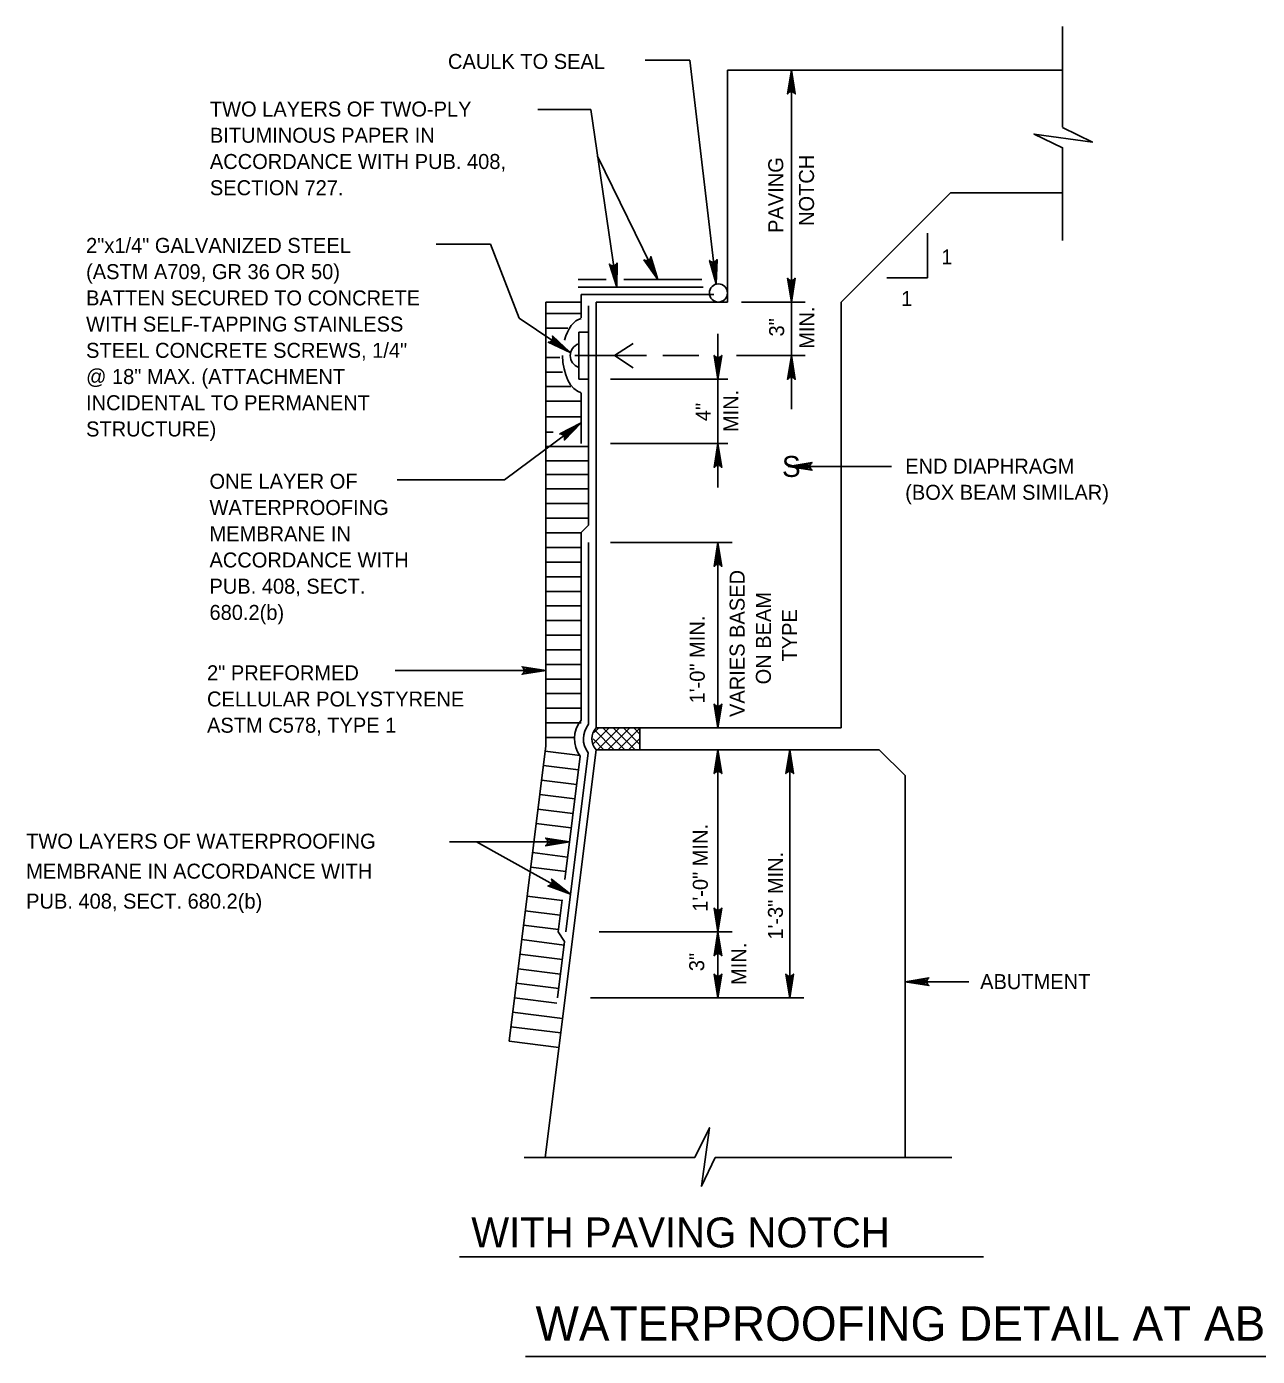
# Model space of a CAD drawing. Extents: x 638653 to 642302, y 298557 to 300414.
# Drawn here: x 641555.5 to 641801.9, y 299693.6 to 299959.8 of the extents above; entities that cross this region are included whole.
import ezdxf

# ---------------------------------------------------------------- set-up
doc = ezdxf.new("R2010")
doc.units = 0
doc.layers.add('1', color=7, linetype='Continuous')

msp = doc.modelspace()

# ---------------------------------------------------------------- linework, layer by layer
at = {"layer": '1'}
for p, q in [((641762.9, 299959.81), (641762.9, 299939.69)), ((641688.27, 299953.06), (641679.3, 299953.06)), ((641688.27, 299953.06), (641693.52, 299908.35)), ((641762.9, 299951.12), (641695.83, 299951.12)), ((641695.83, 299951.12), (641695.83, 299904.66)), ((641708.58, 299951.12), (641708.58, 299904.66)), ((641668.43, 299943.24), (641657.85, 299943.24)), ((641668.43, 299943.24), (641673.61, 299907.66)), ((641762.9, 299916.97), (641762.9, 299935.58)), ((641669.79, 299933.87), (641681.85, 299909.16)), ((641718.59, 299904.66), (641740.48, 299926.55)), ((641762.9, 299926.55), (641740.48, 299926.55)), ((641637.45, 299916.24), (641648.36, 299916.24)), ((641648.36, 299916.24), (641654.07, 299901.48)), ((641735.83, 299909.53), (641735.83, 299918.46)), ((641671.5, 299909.16), (641665.9, 299909.16)), ((641690.65, 299909.16), (641675.01, 299909.16)), ((641727.67, 299909.53), (641735.83, 299909.53)), ((641690.9, 299907.66), (641665.9, 299907.66)), ((641693.08, 299906.16), (641666.5, 299906.16)), ((641666.5, 299901.49), (641666.5, 299906.16)), ((641666.5, 299904.66), (641659.43, 299904.66)), ((641659.43, 299815.83), (641659.43, 299904.66)), ((641666.5, 299902.08), (641666.5, 299904.66)), ((641668, 299860.04), (641668, 299903.95)), ((641669.5, 299819.44), (641669.5, 299904.66)), ((641695.83, 299904.66), (641669.5, 299904.66)), ((641711.33, 299904.66), (641698.6, 299904.66)), ((641708.58, 299904.66), (641708.58, 299893.95)), ((641718.59, 299819.44), (641718.59, 299904.66)), ((641654.07, 299901.48), (641664.3, 299894.6)), ((641659.43, 299902.37), (641666.5, 299902.37)), ((641659.43, 299899.44), (641663.83, 299899.44)), ((641668, 299898.67), (641666.02, 299898.67)), ((641666.02, 299889.23), (641666.02, 299898.67)), ((641693.89, 299889.23), (641693.89, 299898.32)), ((641666.02, 299891.59), (641666.02, 299896.32)), ((641676.94, 299896.41), (641673.16, 299893.95)), ((641659.43, 299893.59), (641662.26, 299893.59)), ((641665.22, 299893.95), (641679.6, 299893.95)), ((641676.94, 299891.49), (641673.16, 299893.95)), ((641682.84, 299893.95), (641690.08, 299893.95)), ((641697.58, 299893.95), (641711.33, 299893.95)), ((641708.58, 299893.95), (641708.58, 299883.24)), ((641659.43, 299890.67), (641662.75, 299890.67)), ((641659.43, 299887.74), (641664.43, 299887.74)), ((641668, 299889.23), (641666.02, 299889.23)), ((641672.38, 299889.23), (641695.88, 299889.23)), ((641693.89, 299876.34), (641693.89, 299889.23)), ((641659.43, 299884.81), (641666.5, 299884.81)), ((641666.5, 299876.34), (641666.5, 299886.41)), ((641659.43, 299881.69), (641666.5, 299881.69)), ((641666.5, 299880.52), (641651.18, 299869.12)), ((641659.43, 299878.66), (641660.86, 299878.66)), ((641672.38, 299876.34), (641695.88, 299876.34)), ((641693.89, 299867.56), (641693.89, 299876.34)), ((641659.43, 299875.74), (641668, 299875.74)), ((641659.43, 299872.91), (641668, 299872.91)), ((641708.57, 299871.76), (641728.61, 299871.76)), ((641629.65, 299869.12), (641651.18, 299869.12)), ((641659.43, 299870.18), (641668, 299870.18)), ((641659.43, 299867.26), (641668, 299867.26)), ((641659.43, 299864.33), (641668, 299864.33)), ((641659.43, 299861.4), (641668, 299861.4)), ((641666.5, 299858.54), (641668, 299860.04)), ((641659.43, 299858.48), (641666.5, 299858.48)), ((641666.5, 299858.54), (641666.5, 299821)), ((641659.43, 299855.55), (641666.5, 299855.55)), ((641668, 299820.17), (641668, 299856.54)), ((641672.38, 299856.54), (641696.71, 299856.54)), ((641693.89, 299856.54), (641693.89, 299819.44)), ((641659.43, 299852.63), (641666.5, 299852.63)), ((641659.43, 299849.7), (641666.5, 299849.7)), ((641659.43, 299846.77), (641666.5, 299846.77)), ((641659.43, 299843.85), (641666.5, 299843.85)), ((641659.43, 299840.92), (641666.5, 299840.92)), ((641659.43, 299838), (641666.5, 299838)), ((641659.43, 299835.07), (641666.5, 299835.07)), ((641629.24, 299830.92), (641659.43, 299830.92)), ((641659.43, 299832.14), (641666.5, 299832.14)), ((641659.43, 299829.22), (641666.5, 299829.22)), ((641659.43, 299826.29), (641666.5, 299826.29)), ((641659.43, 299823.37), (641666.5, 299823.37)), ((641659.43, 299820.44), (641666.5, 299820.44)), ((641659.43, 299817.51), (641665.16, 299817.51)), ((641669, 299816.34), (641672.11, 299819.44)), ((641669.09, 299818.49), (641670.04, 299819.44)), ((641673.14, 299815.05), (641669.25, 299818.95)), ((641718.59, 299819.44), (641669.5, 299819.44)), ((641669.79, 299815.05), (641674.18, 299819.44)), ((641675.21, 299815.05), (641670.82, 299819.44)), ((641671.86, 299815.05), (641676.25, 299819.44)), ((641677.28, 299815.05), (641672.89, 299819.44)), ((641673.93, 299815.05), (641678.32, 299819.44)), ((641678.27, 299816.13), (641674.96, 299819.44)), ((641678.27, 299818.2), (641677.03, 299819.44)), ((641678.27, 299815.05), (641678.27, 299819.44)), ((641652.05, 299756.72), (641659.43, 299815.83)), ((641659.29, 299733.42), (641669.5, 299815.05)), ((641659.31, 299814.79), (641666.31, 299813.92)), ((641671.07, 299815.05), (641668.91, 299817.22)), ((641726.19, 299815.05), (641669.5, 299815.05)), ((641676, 299815.05), (641678.27, 299817.33)), ((641678.06, 299815.05), (641678.27, 299815.26)), ((641693.89, 299778.61), (641693.89, 299815.05)), ((641708.25, 299765.38), (641708.25, 299815.05)), ((641726.19, 299815.05), (641731.35, 299809.9)), ((641663.23, 299789.08), (641666.31, 299813.75)), ((641663.43, 299778.61), (641667.91, 299814.44)), ((641658.94, 299811.89), (641665.95, 299811.01)), ((641731.35, 299733.42), (641731.35, 299809.9)), ((641658.58, 299808.98), (641665.59, 299808.11)), ((641658.22, 299806.08), (641665.22, 299805.21)), ((641657.85, 299803.18), (641664.86, 299802.3)), ((641657.49, 299800.27), (641664.5, 299799.4)), ((641640.15, 299796.62), (641664.17, 299796.62)), ((641664.37, 299786.18), (641645.55, 299796.62)), ((641656.76, 299794.47), (641663.77, 299793.59)), ((641656.4, 299791.56), (641663.41, 299790.69)), ((641655.68, 299785.76), (641662.68, 299784.88)), ((641655.31, 299782.85), (641662.32, 299781.98)), ((641661.92, 299778.6), (641662.72, 299785.01)), ((641654.95, 299779.95), (641661.97, 299779.07)), ((641661.92, 299778.6), (641663.18, 299776.65)), ((641670.09, 299778.61), (641696.71, 299778.61)), ((641693.89, 299765.38), (641693.89, 299778.61)), ((641654.59, 299777.05), (641663.1, 299775.98)), ((641661.78, 299765.38), (641663.18, 299776.65)), ((641654.22, 299774.14), (641662.74, 299773.08)), ((641653.86, 299771.24), (641662.37, 299770.17)), ((641653.5, 299768.34), (641662.01, 299767.27)), ((641731.35, 299768.62), (641744.14, 299768.62)), ((641653.14, 299765.43), (641661.65, 299764.37)), ((641668.34, 299765.38), (641711.07, 299765.38)), ((641652.77, 299762.53), (641662.77, 299761.28)), ((641652.41, 299759.63), (641662.41, 299758.37)), ((641652.05, 299756.72), (641662.05, 299755.47)), ((641655.06, 299733.42), (641689.26, 299733.42)), ((641693.31, 299733.42), (641740.71, 299733.42)), ((641747.04, 299713.57), (641642.11, 299713.57)), ((641655.35, 299693.63), (641994.65, 299693.63))]:
    msp.add_line(p, q, dxfattribs=at)
for points in [[(641709.15, 299946.57), (641708.82, 299946.74), (641708.58, 299951.12), (641709.15, 299946.57), (641709.35, 299946.34), (641708.58, 299951.12), (641708.36, 299946.75), (641708.04, 299946.59), (641708.58, 299951.12), (641707.82, 299946.34), (641708.04, 299946.59)], [(641762.9, 299939.62), (641768.87, 299936.7), (641757.18, 299938.29), (641762.9, 299935.57)], [(641679.34, 299912.99), (641679.71, 299912.98), (641681.85, 299909.16), (641679.34, 299912.99), (641679.06, 299913.11), (641681.85, 299909.16), (641680.13, 299913.18), (641680.35, 299913.47), (641681.85, 299909.16), (641680.44, 299913.78), (641680.35, 299913.47)], [(641672.4, 299912.07), (641672.75, 299911.95), (641673.61, 299907.66), (641672.4, 299912.07), (641672.16, 299912.27), (641673.61, 299907.66), (641673.2, 299912.01), (641673.5, 299912.22), (641673.61, 299907.66), (641673.68, 299912.49), (641673.5, 299912.22)], [(641692.42, 299912.79), (641692.77, 299912.66), (641693.52, 299908.35), (641692.42, 299912.79), (641692.2, 299913), (641693.52, 299908.35), (641693.22, 299912.71), (641693.53, 299912.91), (641693.52, 299908.35), (641693.72, 299913.18), (641693.53, 299912.91)], [(641708.01, 299909.2), (641708.34, 299909.03), (641708.58, 299904.66), (641708.01, 299909.2), (641707.81, 299909.43), (641708.58, 299904.66), (641708.79, 299909.03), (641709.12, 299909.19), (641708.58, 299904.66), (641709.34, 299909.43), (641709.12, 299909.19)], [(641660.21, 299896.66), (641660.53, 299896.84), (641664.3, 299894.6), (641660.21, 299896.66), (641659.91, 299896.63), (641664.3, 299894.6), (641660.79, 299897.22), (641660.84, 299897.58), (641664.3, 299894.6), (641660.76, 299897.9), (641660.84, 299897.58)], [(641693.32, 299893.77), (641693.65, 299893.6), (641693.89, 299889.23), (641693.32, 299893.77), (641693.13, 299894), (641693.89, 299889.23), (641694.11, 299893.6), (641694.44, 299893.76), (641693.89, 299889.23), (641694.65, 299894), (641694.44, 299893.76)], [(641709.15, 299889.41), (641708.82, 299889.58), (641708.58, 299893.95), (641709.15, 299889.41), (641709.35, 299889.18), (641708.58, 299893.95), (641708.36, 299889.58), (641708.04, 299889.42), (641708.58, 299893.95), (641707.82, 299889.18), (641708.04, 299889.42)], [(641663.19, 299877.36), (641663.13, 299877.72), (641666.5, 299880.52), (641663.19, 299877.36), (641663.13, 299877.06), (641666.5, 299880.52), (641662.86, 299878.09), (641662.54, 299878.26), (641666.5, 299880.52), (641662.21, 299878.28), (641662.54, 299878.26)], [(641694.46, 299871.8), (641694.14, 299871.97), (641693.89, 299876.34), (641694.46, 299871.8), (641694.66, 299871.57), (641693.89, 299876.34), (641693.68, 299871.97), (641693.35, 299871.82), (641693.89, 299876.34), (641693.14, 299871.57), (641693.35, 299871.82)], [(641712.5, 299872.33), (641712.33, 299872), (641707.96, 299871.76), (641712.5, 299872.33), (641712.73, 299872.53), (641707.96, 299871.76), (641712.32, 299871.54), (641712.48, 299871.22), (641707.96, 299871.76), (641712.73, 299871), (641712.48, 299871.22)], [(641694.46, 299852), (641694.14, 299852.17), (641693.89, 299856.54), (641694.46, 299852), (641694.66, 299851.77), (641693.89, 299856.54), (641693.68, 299852.17), (641693.35, 299852.01), (641693.89, 299856.54), (641693.14, 299851.77), (641693.35, 299852.01)], [(641654.89, 299830.35), (641655.06, 299830.68), (641659.43, 299830.92), (641654.89, 299830.35), (641654.66, 299830.16), (641659.43, 299830.92), (641655.07, 299831.14), (641654.91, 299831.47), (641659.43, 299830.92), (641654.66, 299831.68), (641654.91, 299831.47)], [(641693.32, 299823.98), (641693.65, 299823.81), (641693.89, 299819.44), (641693.32, 299823.98), (641693.13, 299824.22), (641693.89, 299819.44), (641694.11, 299823.81), (641694.44, 299823.97), (641693.89, 299819.44), (641694.65, 299824.22), (641694.44, 299823.97)], [(641694.46, 299810.51), (641694.14, 299810.68), (641693.89, 299815.05), (641694.46, 299810.51), (641694.66, 299810.28), (641693.89, 299815.05), (641693.68, 299810.69), (641693.35, 299810.53), (641693.89, 299815.05), (641693.14, 299810.28), (641693.35, 299810.53)], [(641708.82, 299810.51), (641708.49, 299810.68), (641708.25, 299815.05), (641708.82, 299810.51), (641709.02, 299810.28), (641708.25, 299815.05), (641708.04, 299810.69), (641707.71, 299810.53), (641708.25, 299815.05), (641707.49, 299810.28), (641707.71, 299810.53)], [(641659.63, 299796.05), (641659.8, 299796.38), (641664.17, 299796.62), (641659.63, 299796.05), (641659.39, 299795.85), (641664.17, 299796.62), (641659.8, 299796.83), (641659.64, 299797.16), (641664.17, 299796.62), (641659.39, 299797.38), (641659.64, 299797.16)], [(641660.13, 299787.88), (641660.43, 299788.09), (641664.37, 299786.18), (641660.13, 299787.88), (641659.83, 299787.82), (641664.37, 299786.18), (641660.66, 299788.48), (641660.68, 299788.85), (641664.37, 299786.18), (641660.57, 299789.16), (641660.68, 299788.85)], [(641693.32, 299783.15), (641693.65, 299782.98), (641693.89, 299778.61), (641693.32, 299783.15), (641693.13, 299783.38), (641693.89, 299778.61), (641694.11, 299782.98), (641694.44, 299783.14), (641693.89, 299778.61), (641694.65, 299783.38), (641694.44, 299783.14)], [(641694.46, 299774.07), (641694.14, 299774.24), (641693.89, 299778.61), (641694.46, 299774.07), (641694.66, 299773.84), (641693.89, 299778.61), (641693.68, 299774.24), (641693.35, 299774.08), (641693.89, 299778.61), (641693.14, 299773.84), (641693.35, 299774.08)], [(641693.32, 299769.92), (641693.65, 299769.76), (641693.89, 299765.38), (641693.32, 299769.92), (641693.13, 299770.16), (641693.89, 299765.38), (641694.11, 299769.75), (641694.44, 299769.91), (641693.89, 299765.38), (641694.65, 299770.16), (641694.44, 299769.91)], [(641707.68, 299769.92), (641708.01, 299769.76), (641708.25, 299765.38), (641707.68, 299769.92), (641707.48, 299770.16), (641708.25, 299765.38), (641708.47, 299769.75), (641708.79, 299769.91), (641708.25, 299765.38), (641709.01, 299770.16), (641708.79, 299769.91)], [(641735.89, 299769.19), (641735.72, 299768.86), (641731.35, 299768.62), (641735.89, 299769.19), (641736.12, 299769.39), (641731.35, 299768.62), (641735.72, 299768.4), (641735.88, 299768.08), (641731.35, 299768.62), (641736.12, 299767.86), (641735.88, 299768.08)], [(641689.26, 299733.42), (641692.18, 299739.39), (641690.59, 299727.7), (641693.31, 299733.42)]]:
    msp.add_lwpolyline(points, dxfattribs=at)
msp.add_circle((641693.99, 299906.49), 1.81, dxfattribs=at)
for centre, major_axis, ratio, start_param, end_param in [((641667.18, 299893.95), (0, -7.54), 0.583333, 3.294264, 4.290154), ((641666.94, 299893.95), (2.63, 0), 0.960038, 1.928978, 4.354207), ((641667.18, 299893.95), (0, -7.54), 0.583333, 4.712384, 6.130513), ((641676.65, 299817.25), (-11.5, 0), 0.694444, 5.794751, 6.735979), ((641675.85, 299817.25), (-8.91, 0), 0.694444, 5.791936, 6.75315), ((641674.97, 299817.25), (-6.32, 0), 0.694444, 5.759587, 6.806784)]:
    msp.add_ellipse(centre, major_axis=major_axis, ratio=ratio, start_param=start_param, end_param=end_param, dxfattribs=at)

# ---------------------------------------------------------------- texts
for s, height, p in [('CAULK TO SEAL', 2.9999, (641639.83, 299951.34)), ('TWO LAYERS OF TWO-PLY', 2.9999, (641592.16, 299941.81)), ('BITUMINOUS PAPER IN', 2.9999, (641592.16, 299936.56)), ('ACCORDANCE WITH PUB. 408,', 2.9999, (641592.16, 299931.31)), ('SECTION 727.', 2.9999, (641592.16, 299926.06)), ('2"x1/4" GALVANIZED STEEL', 2.9999, (641567.37, 299914.51)), ('1', 3, (641738.61, 299912.21)), ('(ASTM A709, GR 36 OR 50) ', 2.9999, (641567.37, 299909.26)), ('BATTEN SECURED TO CONCRETE', 2.9999, (641567.37, 299904.01)), ('1', 3, (641730.58, 299903.88)), ('WITH SELF-TAPPING STAINLESS', 2.9999, (641567.37, 299898.76)), ('STEEL CONCRETE SCREWS, 1/4" ', 2.9999, (641567.37, 299893.51)), ('@ 18" MAX. (ATTACHMENT ', 2.9999, (641567.37, 299888.27)), ('INCIDENTAL TO PERMANENT', 2.9999, (641567.37, 299883.02)), ('STRUCTURE)', 3, (641567.37, 299877.77)), ('S', 4.2, (641706.7, 299869.67)), ('END DIAPHRAGM', 2.9999, (641731.38, 299870.33)), ('ONE LAYER OF', 2.9999, (641592.08, 299867.3)), ('(BOX BEAM SIMILAR)', 2.9999, (641731.38, 299865.09)), ('WATERPROOFING', 2.9999, (641592.08, 299862.05)), ('MEMBRANE IN', 2.9999, (641592.08, 299856.8)), ('ACCORDANCE WITH', 2.9999, (641592.08, 299851.55)), ('PUB. 408, SECT.', 2.9999, (641592.08, 299846.3)), ('680.2(b)', 3, (641592.08, 299841.05)), ('2" PREFORMED', 2.9999, (641591.59, 299828.97)), ('CELLULAR POLYSTYRENE', 2.9999, (641591.59, 299823.72)), ('ASTM C578, TYPE 1', 2.9999, (641591.59, 299818.47)), ('TWO LAYERS OF WATERPROOFING', 3, (641555.37, 299795.26)), ('MEMBRANE IN ACCORDANCE WITH', 3, (641555.37, 299789.26)), ('PUB. 408, SECT. 680.2(b)', 3, (641555.37, 299783.26)), ('ABUTMENT', 3, (641746.39, 299767.15)), ('WITH PAVING NOTCH', 6, (641644.5, 299715.44)), ('WATERPROOFING DETAIL AT ABUTMENT WITHOUT BACKWALL', 6.8753, (641657.37, 299696.77))]:
    msp.add_text(s, height=height, dxfattribs=at).set_placement(p)
for s, height, p in [('PAVING', 3, (641706.96, 299918.51)), ('NOTCH', 3, (641713.12, 299919.9)), ('MIN.', 3, (641713.21, 299895.32)), ('3"', 3, (641707.14, 299897.78)), ('MIN.', 3, (641697.97, 299878.65)), ('4"', 3, (641692.4, 299880.84)), ('VARIES BASED', 2.9999, (641699.23, 299821.62)), ('ON BEAM', 3, (641704.48, 299828.15)), ('1\'-0" MIN.', 3, (641691.24, 299824.34)), ('TYPE', 3, (641709.73, 299832.73)), ('1\'-0" MIN.', 3, (641691.85, 299782.64)), ('1\'-3" MIN.', 3, (641706.9, 299777.06)), ('MIN.', 3, (641699.54, 299767.98)), ('3"', 3, (641691.14, 299770.74))]:
    msp.add_text(s, height=height, rotation=90, dxfattribs=at).set_placement(p)

doc.saveas('drawing.dxf')
